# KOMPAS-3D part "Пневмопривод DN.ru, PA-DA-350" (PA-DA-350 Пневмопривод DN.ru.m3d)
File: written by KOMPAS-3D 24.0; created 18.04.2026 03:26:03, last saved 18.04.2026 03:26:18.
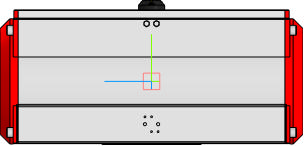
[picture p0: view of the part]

Document properties: Автор: DN.ru; Полное имя файла: C:\Работа\PA-DA-х Пневмопривод DN.ru\350\PA-DA-350 Пневмопривод DN.ru.m3d

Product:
- Part/product: Пневмопривод DN.ru  | designation PA-DA-350
    Масса: 186
    Раздел спецификации: Прочие изделия
    Примечание: D290-00303

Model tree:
1. Операция без истории:1

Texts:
  PA-DA-350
